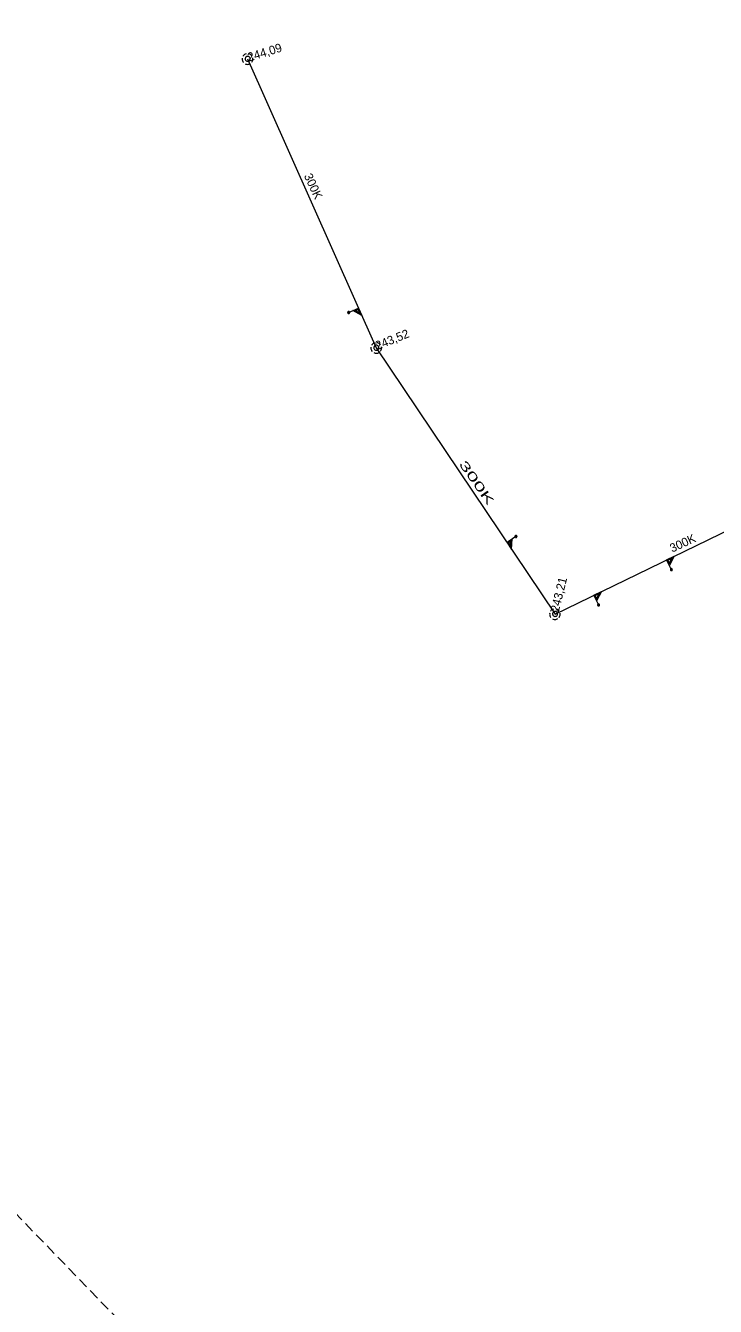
# Model space of a CAD drawing. Extents: x -735085 to -733500, y -1044153 to -1043402.
# Drawn here: x -734892.7 to -734828.8, y -1043715.9 to -1043597 of the extents above; entities that cross this region are included whole.
import ezdxf

# ---------------------------------------------------------------- set-up
doc = ezdxf.new("R2010")
doc.units = 0
doc.header["$LTSCALE"] = 0.32
doc.linetypes.add('MEDIUM_DASHED', pattern=[4.5, 3, -1.5])
doc.layers.add('16', color=7, linetype='Continuous')
for name, color, linetype, lineweight in [('18', 7, 'Continuous', 13), ('20', 7, 'Continuous', 13), ('63', 7, 'MEDIUM_DASHED', 25)]:
    doc.layers.add(name, color=color, linetype=linetype, lineweight=lineweight)

msp = doc.modelspace()

# ---------------------------------------------------------------- linework, layer by layer
at = {"layer": '18'}
for points in [[(-734872.302, -1043599.647), (-734872.373, -1043599.675), (-734872.44, -1043599.714), (-734872.5, -1043599.762), (-734872.551, -1043599.819), (-734872.575, -1043599.853)], [(-734871.761, -1043599.83), (-734871.811, -1043599.772), (-734871.869, -1043599.722), (-734871.934, -1043599.681), (-734872.005, -1043599.652), (-734872.054, -1043599.638)], [(-734872.647, -1043600.039), (-734872.652, -1043600.116), (-734872.647, -1043600.193), (-734872.63, -1043600.268), (-734872.602, -1043600.339), (-734872.561, -1043600.405), (-734872.546, -1043600.427)], [(-734872.389, -1043600.556), (-734872.319, -1043600.587), (-734872.244, -1043600.606), (-734872.168, -1043600.613), (-734872.091, -1043600.608), (-734872.016, -1043600.591), (-734871.944, -1043600.563), (-734871.884, -1043600.528)], [(-734871.766, -1043600.416), (-734871.725, -1043600.351), (-734871.694, -1043600.281), (-734871.674, -1043600.206), (-734871.667, -1043600.13), (-734871.672, -1043600.053), (-734871.678, -1043600.018)], [(-734862.866, -1043623.674), (-734861.866, -1043623.228), (-734861.553, -1043623.932), (-734862.394, -1043623.463)], [(-734862.266, -1043623.461), (-734861.886, -1043623.292), (-734861.656, -1043623.809), (-734862.267, -1043623.462)], [(-734862.17, -1043623.47), (-734861.903, -1043623.351), (-734861.752, -1043623.691), (-734862.171, -1043623.469)], [(-734860.717, -1043626.849), (-734860.723, -1043626.926), (-734860.718, -1043627.003), (-734860.701, -1043627.078), (-734860.672, -1043627.149), (-734860.632, -1043627.215), (-734860.616, -1043627.237)], [(-734860.372, -1043626.457), (-734860.443, -1043626.485), (-734860.51, -1043626.524), (-734860.57, -1043626.572), (-734860.621, -1043626.629), (-734860.645, -1043626.663)], [(-734859.831, -1043626.64), (-734859.881, -1043626.582), (-734859.939, -1043626.532), (-734860.004, -1043626.491), (-734860.075, -1043626.462), (-734860.124, -1043626.448)], [(-734859.836, -1043627.226), (-734859.795, -1043627.161), (-734859.764, -1043627.091), (-734859.745, -1043627.016), (-734859.737, -1043626.94), (-734859.742, -1043626.863), (-734859.748, -1043626.828)], [(-734860.459, -1043627.366), (-734860.389, -1043627.397), (-734860.314, -1043627.416), (-734860.238, -1043627.423), (-734860.161, -1043627.418), (-734860.086, -1043627.401), (-734860.014, -1043627.373), (-734859.954, -1043627.338)], [(-734847.187, -1043644.367), (-734848.096, -1043644.977), (-734847.666, -1043645.618), (-734847.616, -1043644.655)], [(-734847.686, -1043644.764), (-734848.032, -1043644.996), (-734847.716, -1043645.466), (-734847.685, -1043644.763)], [(-734847.729, -1043644.849), (-734847.971, -1043645.012), (-734847.765, -1043645.32), (-734847.729, -1043644.848)], [(-734832.817, -1043647.582), (-734833.295, -1043646.597), (-734832.603, -1043646.26), (-734833.043, -1043647.117)], [(-734833.049, -1043646.989), (-734833.231, -1043646.615), (-734832.722, -1043646.367), (-734833.049, -1043646.99)], [(-734833.044, -1043646.893), (-734833.171, -1043646.63), (-734832.837, -1043646.468), (-734833.045, -1043646.893)], [(-734839.563, -1043650.861), (-734840.041, -1043649.876), (-734839.349, -1043649.539), (-734839.789, -1043650.396)], [(-734839.795, -1043650.268), (-734839.977, -1043649.894), (-734839.468, -1043649.646), (-734839.795, -1043650.269)], [(-734839.79, -1043650.172), (-734839.917, -1043649.909), (-734839.583, -1043649.747), (-734839.791, -1043650.172)], [(-734844.138, -1043651.549), (-734844.144, -1043651.626), (-734844.139, -1043651.703), (-734844.122, -1043651.778), (-734844.093, -1043651.849), (-734844.053, -1043651.915), (-734844.037, -1043651.937)], [(-734843.793, -1043651.157), (-734843.864, -1043651.185), (-734843.931, -1043651.224), (-734843.991, -1043651.272), (-734844.042, -1043651.329), (-734844.066, -1043651.363)], [(-734843.88, -1043652.066), (-734843.81, -1043652.097), (-734843.735, -1043652.116), (-734843.659, -1043652.123), (-734843.582, -1043652.118), (-734843.507, -1043652.101), (-734843.435, -1043652.073), (-734843.375, -1043652.038)], [(-734843.252, -1043651.34), (-734843.302, -1043651.282), (-734843.36, -1043651.232), (-734843.425, -1043651.191), (-734843.496, -1043651.162), (-734843.545, -1043651.148)], [(-734843.257, -1043651.926), (-734843.216, -1043651.861), (-734843.185, -1043651.791), (-734843.166, -1043651.716), (-734843.158, -1043651.64), (-734843.163, -1043651.563), (-734843.169, -1043651.528)]]:
    msp.add_lwpolyline(points, dxfattribs=at)
for points in [[(-734871.918, -1043600.099), (-734871.924, -1043600.047), (-734871.941, -1043599.997), (-734871.97, -1043599.953), (-734872.008, -1043599.916), (-734872.053, -1043599.889), (-734872.103, -1043599.873), (-734872.155, -1043599.868), (-734872.206, -1043599.875), (-734872.255, -1043599.894), (-734872.299, -1043599.924), (-734872.335, -1043599.963), (-734872.361, -1043600.008), (-734872.375, -1043600.059), (-734872.379, -1043600.111), (-734872.37, -1043600.163), (-734872.35, -1043600.211), (-734872.32, -1043600.254), (-734872.28, -1043600.289), (-734872.233, -1043600.313), (-734872.183, -1043600.327), (-734872.13, -1043600.329), (-734872.079, -1043600.319), (-734872.031, -1043600.297), (-734871.989, -1043600.265), (-734871.956, -1043600.225), (-734871.932, -1043600.178), (-734871.919, -1043600.127)], [(-734862.742, -1043623.721), (-734862.715, -1043623.702), (-734862.695, -1043623.675), (-734862.686, -1043623.643), (-734862.69, -1043623.609), (-734862.705, -1043623.58), (-734862.729, -1043623.557), (-734862.76, -1043623.543), (-734862.794, -1043623.542), (-734862.825, -1043623.552), (-734862.851, -1043623.573), (-734862.869, -1043623.601), (-734862.875, -1043623.635), (-734862.869, -1043623.667), (-734862.853, -1043623.697), (-734862.827, -1043623.718), (-734862.795, -1043623.728), (-734862.761, -1043623.728)], [(-734862.752, -1043623.696), (-734862.729, -1043623.679), (-734862.715, -1043623.655), (-734862.713, -1043623.627), (-734862.722, -1043623.6), (-734862.741, -1043623.579), (-734862.767, -1043623.569), (-734862.796, -1043623.57), (-734862.821, -1043623.582), (-734862.839, -1043623.603), (-734862.846, -1043623.631), (-734862.842, -1043623.659), (-734862.827, -1043623.683), (-734862.803, -1043623.698), (-734862.776, -1043623.702)], [(-734859.988, -1043626.909), (-734859.994, -1043626.857), (-734860.012, -1043626.807), (-734860.04, -1043626.763), (-734860.078, -1043626.726), (-734860.123, -1043626.699), (-734860.173, -1043626.683), (-734860.225, -1043626.678), (-734860.277, -1043626.685), (-734860.326, -1043626.704), (-734860.37, -1043626.734), (-734860.405, -1043626.773), (-734860.431, -1043626.818), (-734860.446, -1043626.869), (-734860.449, -1043626.921), (-734860.441, -1043626.973), (-734860.42, -1043627.021), (-734860.39, -1043627.064), (-734860.35, -1043627.099), (-734860.304, -1043627.123), (-734860.253, -1043627.137), (-734860.201, -1043627.139), (-734860.149, -1043627.129), (-734860.101, -1043627.107), (-734860.059, -1043627.075), (-734860.026, -1043627.035), (-734860.002, -1043626.988), (-734859.99, -1043626.937)], [(-734847.212, -1043644.498), (-734847.188, -1043644.475), (-734847.173, -1043644.445), (-734847.17, -1043644.412), (-734847.18, -1043644.379), (-734847.199, -1043644.353), (-734847.227, -1043644.334), (-734847.26, -1043644.326), (-734847.293, -1043644.33), (-734847.323, -1043644.345), (-734847.345, -1043644.371), (-734847.357, -1043644.402), (-734847.358, -1043644.435), (-734847.346, -1043644.467), (-734847.325, -1043644.493), (-734847.296, -1043644.509), (-734847.262, -1043644.514), (-734847.229, -1043644.508)], [(-734847.228, -1043644.477), (-734847.208, -1043644.457), (-734847.199, -1043644.43), (-734847.201, -1043644.402), (-734847.215, -1043644.377), (-734847.237, -1043644.36), (-734847.265, -1043644.353), (-734847.292, -1043644.359), (-734847.316, -1043644.376), (-734847.329, -1043644.4), (-734847.333, -1043644.428), (-734847.324, -1043644.456), (-734847.305, -1043644.476), (-734847.279, -1043644.487), (-734847.25, -1043644.487)], [(-734832.773, -1043647.456), (-734832.793, -1043647.429), (-734832.821, -1043647.411), (-734832.854, -1043647.403), (-734832.887, -1043647.408), (-734832.916, -1043647.423), (-734832.938, -1043647.449), (-734832.951, -1043647.48), (-734832.951, -1043647.514), (-734832.939, -1043647.545), (-734832.918, -1043647.57), (-734832.889, -1043647.587), (-734832.855, -1043647.592), (-734832.823, -1043647.585), (-734832.794, -1043647.567), (-734832.773, -1043647.541), (-734832.765, -1043647.509), (-734832.766, -1043647.475)], [(-734832.798, -1043647.467), (-734832.816, -1043647.445), (-734832.84, -1043647.431), (-734832.868, -1043647.43), (-734832.895, -1043647.44), (-734832.915, -1043647.46), (-734832.924, -1043647.486), (-734832.923, -1043647.514), (-734832.91, -1043647.539), (-734832.888, -1043647.556), (-734832.86, -1043647.563), (-734832.833, -1043647.558), (-734832.809, -1043647.543), (-734832.795, -1043647.518), (-734832.791, -1043647.49)], [(-734839.519, -1043650.735), (-734839.539, -1043650.708), (-734839.567, -1043650.69), (-734839.6, -1043650.682), (-734839.633, -1043650.687), (-734839.662, -1043650.702), (-734839.684, -1043650.728), (-734839.697, -1043650.759), (-734839.697, -1043650.793), (-734839.685, -1043650.824), (-734839.664, -1043650.849), (-734839.635, -1043650.866), (-734839.601, -1043650.871), (-734839.569, -1043650.864), (-734839.54, -1043650.846), (-734839.519, -1043650.82), (-734839.511, -1043650.788), (-734839.512, -1043650.754)], [(-734839.544, -1043650.746), (-734839.562, -1043650.724), (-734839.586, -1043650.71), (-734839.614, -1043650.709), (-734839.641, -1043650.719), (-734839.661, -1043650.739), (-734839.67, -1043650.765), (-734839.669, -1043650.793), (-734839.656, -1043650.818), (-734839.634, -1043650.835), (-734839.606, -1043650.842), (-734839.579, -1043650.837), (-734839.555, -1043650.822), (-734839.541, -1043650.797), (-734839.537, -1043650.769)], [(-734843.409, -1043651.609), (-734843.415, -1043651.557), (-734843.433, -1043651.507), (-734843.461, -1043651.463), (-734843.499, -1043651.426), (-734843.544, -1043651.399), (-734843.594, -1043651.383), (-734843.646, -1043651.378), (-734843.698, -1043651.385), (-734843.747, -1043651.404), (-734843.791, -1043651.434), (-734843.826, -1043651.473), (-734843.852, -1043651.518), (-734843.867, -1043651.569), (-734843.87, -1043651.621), (-734843.862, -1043651.673), (-734843.841, -1043651.721), (-734843.811, -1043651.764), (-734843.771, -1043651.799), (-734843.725, -1043651.823), (-734843.674, -1043651.837), (-734843.622, -1043651.839), (-734843.57, -1043651.829), (-734843.522, -1043651.807), (-734843.48, -1043651.775), (-734843.447, -1043651.735), (-734843.423, -1043651.688), (-734843.411, -1043651.637)]]:
    msp.add_lwpolyline(points, close=True, dxfattribs=at)
at = {"layer": '20'}
for p, q in [((-734872.149, -1043600.11), (-734860.219, -1043626.92)), ((-734872.149, -1043600.11), (-734860.219, -1043626.92)), ((-734860.219, -1043626.92), (-734843.64, -1043651.62)), ((-734860.219, -1043626.92), (-734843.64, -1043651.62)), ((-734843.64, -1043651.62), (-734818.35, -1043639.33)), ((-734843.64, -1043651.62), (-734818.35, -1043639.33))]:
    msp.add_line(p, q, dxfattribs=at)
at = {"layer": '63'}
msp.add_lwpolyline([(-734796.022, -1043808.279), (-734957.658, -1043641.023), (-734957.66, -1043641.021), (-735032.487, -1043496.398), (-735032.488, -1043496.396), (-735032.488, -1043496.394), (-735032.488, -1043496.393), (-735032.488, -1043496.391), (-735014.686, -1043433.916), (-735014.686, -1043433.914), (-735014.685, -1043433.913), (-735014.683, -1043433.911), (-735014.682, -1043433.91), (-735014.68, -1043433.909), (-735014.678, -1043433.909), (-735014.676, -1043433.909), (-734957.569, -1043435.5), (-734957.567, -1043435.5), (-734957.565, -1043435.501), (-734250.468, -1043761.931)], dxfattribs=at)

# ---------------------------------------------------------------- texts
at = {"layer": '16'}
for s, rotation, p in [('244,09', 17, (-734872.023, -1043600.357)), ('300K', 295, (-734866.952, -1043610.957)), ('243,52', 22, (-734860.119, -1043627.13)), ('300K', 25, (-734832.773, -1043645.928)), ('243,21', 76, (-734843.309, -1043651.497))]:
    msp.add_text(s, height=0.8, rotation=rotation, dxfattribs=at).set_placement(p)
at = {"layer": '16', "width": 1.9}
msp.add_text('300K', height=0.8, rotation=305, dxfattribs=at).set_placement((-734852.595, -1043637.707))

doc.saveas('drawing.dxf')
